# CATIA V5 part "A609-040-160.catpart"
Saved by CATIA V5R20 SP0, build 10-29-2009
Part number: A609-040-160
Source: Unknown
Property "ARTICLENO": "A609-040-160"
Property "B": "30.000"
Property "BOMINFO": "A609-040-160"
Property "CODE": "A609-040-160"
Property "D": "20.000"
Property "D1": "13.500"
Property "FORM": "A"
Property "L": "160.000"
Property "L1": "25.000"
Property "L2": "110.000"
Property "LINA": "A609-040-160"
Property "NB": "A609-040-160"
Property "NBSYN": "$CODE."
Property "NN": "A609"
Property "NT": "VDI 3357 E-Type Wear Plates, self-lubricating"
Property "S": "40.000"
Property "SUPPLIER": "CF"
Property "T": "13.000"
Property "W": "60.000"
Bounding box of the stored display mesh (mm): x 0 to 160, y 0 to 40, z 0 to 60
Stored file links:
  C:\Users\Utente\Desktop\3D files A609\A609-040-160.catpart
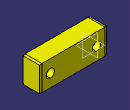
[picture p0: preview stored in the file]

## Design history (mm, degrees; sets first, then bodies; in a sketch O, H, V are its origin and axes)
Body1 "Geometry.1" (main body)
  Solid1 "A609-040-160.catpart": solid without history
